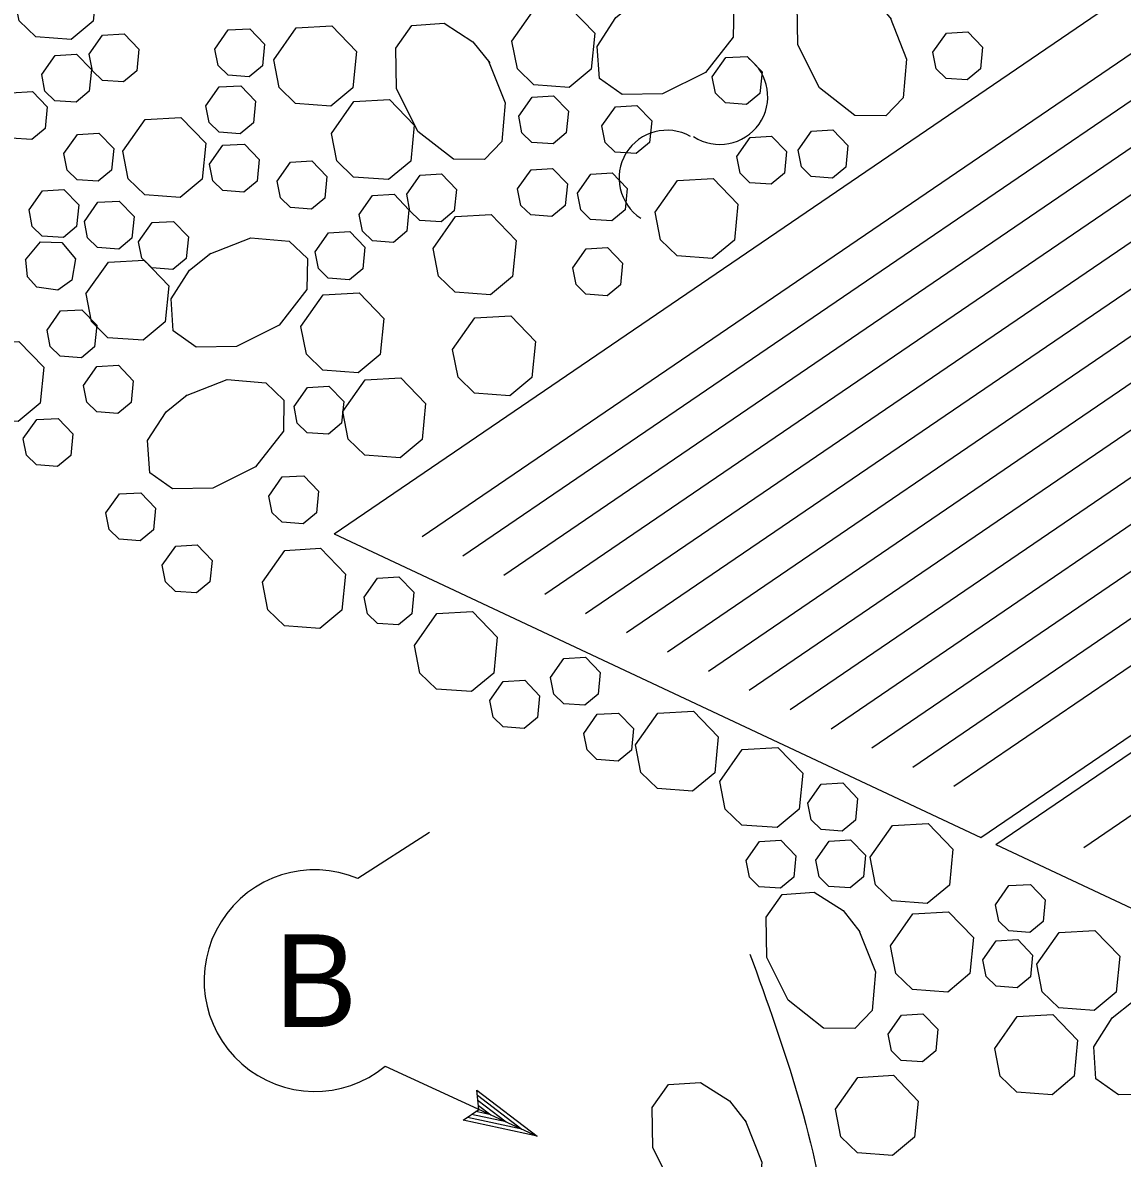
# Model space of a CAD drawing. Extents: x 6707406 to 6714471, y 1868570 to 1872341.
# Drawn here: x 6709742.1 to 6709827.6, y 1870177.2 to 1870265.6 of the extents above; entities that cross this region are included whole.
import ezdxf

# ---------------------------------------------------------------- set-up
doc = ezdxf.new("R2010")
doc.units = 0
for name, color, linetype in [('56 Stg 3 Anno', 7, 'Continuous'), ('57 Undefined', 7, 'Continuous'), ('60 Nongeo Data', 7, 'Continuous')]:
    doc.layers.add(name, color=color, linetype=linetype)

msp = doc.modelspace()

# ---------------------------------------------------------------- linework, layer by layer
at = {"layer": '56 Stg 3 Anno'}
for p, q in [((6709773.692, 1870202.586), (6709768.131, 1870199.006)), ((6709770.255, 1870184.412), (6709782.088, 1870178.964)), ((6709777.549, 1870181.053), (6709777.39, 1870182.544)), ((6709777.39, 1870182.544), (6709777.39, 1870182.544)), ((6709777.39, 1870182.544), (6709782.088, 1870178.964)), ((6709777.435, 1870182.146), (6709780.884, 1870179.519)), ((6709777.496, 1870181.738), (6709779.677, 1870180.075)), ((6709776.318, 1870180.214), (6709777.549, 1870181.053)), ((6709778.472, 1870180.632), (6709777.31, 1870180.883)), ((6709777.511, 1870181.365), (6709778.472, 1870180.632)), ((6709782.088, 1870178.964), (6709776.318, 1870180.214)), ((6709776.318, 1870180.214), (6709776.318, 1870180.214)), ((6709780.872, 1870179.52), (6709776.666, 1870180.433)), ((6709779.677, 1870180.075), (6709776.96, 1870180.664)), ((6709782.088, 1870178.964), (6709782.088, 1870178.964))]:
    msp.add_line(p, q, dxfattribs=at)
msp.add_arc((6709764.782, 1870191.067), 8.617, 67.12615, 309.43269, dxfattribs=at)
at = {"layer": '60 Nongeo Data'}
for p, q in [((6709766.295, 1870225.831), (6709844.223, 1870278.945)), ((6709773.125, 1870225.604), (6709845.802, 1870275.139)), ((6709776.307, 1870224.111), (6709848.983, 1870273.644)), ((6709779.488, 1870222.617), (6709852.164, 1870272.151)), ((6709782.67, 1870221.123), (6709855.345, 1870270.657)), ((6709785.85, 1870219.629), (6709858.526, 1870269.163)), ((6709789.032, 1870218.135), (6709861.708, 1870267.67)), ((6709792.212, 1870216.642), (6709864.888, 1870266.176)), ((6709795.394, 1870215.148), (6709868.07, 1870264.682)), ((6709798.575, 1870213.654), (6709871.251, 1870263.189)), ((6709801.757, 1870212.16), (6709874.433, 1870261.694)), ((6709804.938, 1870210.666), (6709877.614, 1870260.2)), ((6709808.119, 1870209.172), (6709880.795, 1870258.707)), ((6709811.3, 1870207.679), (6709883.975, 1870257.213)), ((6709814.481, 1870206.185), (6709887.158, 1870255.719)), ((6709816.605, 1870202.207), (6709894.532, 1870255.321)), ((6709817.773, 1870201.659), (6709895.701, 1870254.773)), ((6709824.603, 1870201.432), (6709897.278, 1870250.967)), ((6709766.295, 1870225.831), (6709816.605, 1870202.207)), ((6709817.773, 1870201.659), (6709868.082, 1870178.035))]:
    msp.add_line(p, q, dxfattribs=at)
for points in [[(6709741.368, 1870267.869), (6709743.108, 1870270.344), (6709745.884, 1870270.503), (6709747.816, 1870268.501), (6709747.536, 1870265.696), (6709745.821, 1870264.269), (6709743.078, 1870264.469), (6709741.789, 1870265.719), (6709741.37, 1870267.869)], [(6709789.703, 1870267.206), (6709792.956, 1870268.496), (6709795.946, 1870268.237), (6709797.366, 1870266.887), (6709797.321, 1870264.461), (6709795.165, 1870261.706), (6709791.832, 1870260.039), (6709788.693, 1870259.984), (6709786.925, 1870261.24), (6709786.757, 1870263.742), (6709788.192, 1870265.979), (6709789.835, 1870267.289)], [(6709809.532, 1870265.987), (6709810.822, 1870262.734), (6709810.563, 1870259.744), (6709809.212, 1870258.324), (6709806.788, 1870258.369), (6709804.032, 1870260.525), (6709802.365, 1870263.858), (6709802.31, 1870266.998), (6709803.566, 1870268.765), (6709806.068, 1870268.933), (6709808.304, 1870267.499), (6709809.615, 1870265.856)], [(6709780.115, 1870264.136), (6709781.855, 1870266.611), (6709784.631, 1870266.77), (6709786.562, 1870264.767), (6709786.283, 1870261.963), (6709784.567, 1870260.536), (6709781.825, 1870260.735), (6709780.535, 1870261.986), (6709780.116, 1870264.136)], [(6709778.304, 1870262.592), (6709779.594, 1870259.338), (6709779.335, 1870256.349), (6709777.985, 1870254.928), (6709775.559, 1870254.973), (6709772.804, 1870257.13), (6709771.138, 1870260.463), (6709771.082, 1870263.602), (6709772.338, 1870265.37), (6709774.84, 1870265.537), (6709777.077, 1870264.104), (6709778.387, 1870262.461)], [(6709747.226, 1870263.137), (6709748.27, 1870264.621), (6709749.936, 1870264.717), (6709751.095, 1870263.515), (6709750.927, 1870261.833), (6709749.899, 1870260.977), (6709748.252, 1870261.096), (6709747.478, 1870261.846), (6709747.227, 1870263.136)], [(6709757.001, 1870263.53), (6709758.045, 1870265.014), (6709759.712, 1870265.11), (6709760.87, 1870263.908), (6709760.702, 1870262.227), (6709759.674, 1870261.37), (6709758.028, 1870261.489), (6709757.254, 1870262.24), (6709757.003, 1870263.53)], [(6709761.578, 1870262.701), (6709763.317, 1870265.175), (6709766.094, 1870265.334), (6709768.024, 1870263.333), (6709767.745, 1870260.527), (6709766.03, 1870259.1), (6709763.287, 1870259.299), (6709761.997, 1870260.55), (6709761.58, 1870262.7)], [(6709812.868, 1870263.288), (6709813.912, 1870264.773), (6709815.578, 1870264.868), (6709816.736, 1870263.667), (6709816.569, 1870261.984), (6709815.539, 1870261.129), (6709813.894, 1870261.247), (6709813.121, 1870261.998), (6709812.869, 1870263.288)], [(6709743.53, 1870261.552), (6709744.574, 1870263.036), (6709746.24, 1870263.132), (6709747.399, 1870261.93), (6709747.23, 1870260.248), (6709746.202, 1870259.392), (6709744.556, 1870259.511), (6709743.782, 1870260.261), (6709743.531, 1870261.551)], [(6709795.702, 1870261.381), (6709796.747, 1870262.865), (6709798.413, 1870262.96), (6709799.571, 1870261.76), (6709799.403, 1870260.077), (6709798.374, 1870259.22), (6709796.728, 1870259.34), (6709795.954, 1870260.09), (6709795.703, 1870261.381)], [(6709740.098, 1870258.647), (6709741.142, 1870260.13), (6709742.808, 1870260.226), (6709743.967, 1870259.024), (6709743.799, 1870257.343), (6709742.771, 1870256.486), (6709741.124, 1870256.606), (6709740.35, 1870257.356), (6709740.099, 1870258.646)], [(6709756.305, 1870259.102), (6709757.349, 1870260.587), (6709759.015, 1870260.682), (6709760.173, 1870259.481), (6709760.006, 1870257.798), (6709758.976, 1870256.941), (6709757.331, 1870257.062), (6709756.557, 1870257.812), (6709756.306, 1870259.102)], [(6709766.072, 1870256.974), (6709767.812, 1870259.449), (6709770.588, 1870259.608), (6709772.519, 1870257.605), (6709772.24, 1870254.801), (6709770.524, 1870253.374), (6709767.782, 1870253.573), (6709766.492, 1870254.824), (6709766.074, 1870256.974)], [(6709780.642, 1870258.316), (6709781.686, 1870259.8), (6709783.352, 1870259.896), (6709784.511, 1870258.694), (6709784.343, 1870257.012), (6709783.315, 1870256.156), (6709781.668, 1870256.275), (6709780.894, 1870257.025), (6709780.643, 1870258.315)], [(6709787.12, 1870257.564), (6709788.164, 1870259.049), (6709789.83, 1870259.144), (6709790.988, 1870257.943), (6709790.821, 1870256.26), (6709789.791, 1870255.404), (6709788.145, 1870255.523), (6709787.372, 1870256.273), (6709787.121, 1870257.564)], [(6709749.842, 1870255.58), (6709751.58, 1870258.054), (6709754.358, 1870258.213), (6709756.288, 1870256.212), (6709756.008, 1870253.406), (6709754.293, 1870251.979), (6709751.551, 1870252.179), (6709750.261, 1870253.429), (6709749.843, 1870255.579)], [(6709745.265, 1870255.411), (6709746.309, 1870256.895), (6709747.975, 1870256.991), (6709749.134, 1870255.789), (6709748.965, 1870254.107), (6709747.937, 1870253.25), (6709746.291, 1870253.37), (6709745.517, 1870254.12), (6709745.266, 1870255.41)], [(6709797.61, 1870255.179), (6709798.654, 1870256.663), (6709800.32, 1870256.758), (6709801.478, 1870255.557), (6709801.311, 1870253.875), (6709800.281, 1870253.019), (6709798.635, 1870253.137), (6709797.862, 1870253.888), (6709797.611, 1870255.179)], [(6709802.378, 1870255.657), (6709803.422, 1870257.141), (6709805.088, 1870257.235), (6709806.246, 1870256.035), (6709806.079, 1870254.352), (6709805.049, 1870253.496), (6709803.404, 1870253.615), (6709802.63, 1870254.366), (6709802.379, 1870255.657)], [(6709756.589, 1870254.564), (6709757.633, 1870256.049), (6709759.299, 1870256.143), (6709760.457, 1870254.943), (6709760.29, 1870253.26), (6709759.26, 1870252.404), (6709757.615, 1870252.523), (6709756.841, 1870253.273), (6709756.591, 1870254.564)], [(6709761.849, 1870253.245), (6709762.893, 1870254.73), (6709764.559, 1870254.825), (6709765.717, 1870253.624), (6709765.55, 1870251.941), (6709764.521, 1870251.085), (6709762.875, 1870251.205), (6709762.101, 1870251.955), (6709761.85, 1870253.245)], [(6709780.559, 1870252.664), (6709781.602, 1870254.148), (6709783.269, 1870254.245), (6709784.427, 1870253.042), (6709784.259, 1870251.36), (6709783.231, 1870250.504), (6709781.584, 1870250.623), (6709780.811, 1870251.373), (6709780.56, 1870252.663)], [(6709771.93, 1870252.241), (6709772.974, 1870253.725), (6709774.64, 1870253.821), (6709775.799, 1870252.619), (6709775.63, 1870250.937), (6709774.602, 1870250.081), (6709772.956, 1870250.2), (6709772.182, 1870250.95), (6709771.931, 1870252.241)], [(6709785.212, 1870252.317), (6709786.257, 1870253.801), (6709787.923, 1870253.896), (6709789.081, 1870252.695), (6709788.913, 1870251.012), (6709787.884, 1870250.156), (6709786.238, 1870250.275), (6709785.465, 1870251.026), (6709785.213, 1870252.317)], [(6709791.251, 1870250.839), (6709792.989, 1870253.313), (6709795.767, 1870253.471), (6709797.696, 1870251.47), (6709797.417, 1870248.666), (6709795.702, 1870247.239), (6709792.96, 1870247.437), (6709791.669, 1870248.688), (6709791.252, 1870250.839)], [(6709742.549, 1870251.029), (6709743.591, 1870252.512), (6709745.259, 1870252.608), (6709746.416, 1870251.406), (6709746.249, 1870249.724), (6709745.22, 1870248.868), (6709743.574, 1870248.987), (6709742.799, 1870249.737), (6709742.549, 1870251.027)], [(6709768.233, 1870250.656), (6709769.277, 1870252.14), (6709770.944, 1870252.236), (6709772.103, 1870251.034), (6709771.934, 1870249.353), (6709770.906, 1870248.496), (6709769.26, 1870248.615), (6709768.486, 1870249.365), (6709768.235, 1870250.656)], [(6709746.849, 1870250.128), (6709747.893, 1870251.612), (6709749.559, 1870251.708), (6709750.718, 1870250.506), (6709750.55, 1870248.825), (6709749.522, 1870247.968), (6709747.875, 1870248.087), (6709747.101, 1870248.837), (6709746.85, 1870250.127)], [(6709773.994, 1870248.018), (6709775.732, 1870250.493), (6709778.51, 1870250.65), (6709780.441, 1870248.649), (6709780.162, 1870245.845), (6709778.447, 1870244.418), (6709775.704, 1870244.616), (6709774.414, 1870245.867), (6709773.995, 1870248.018)], [(6709751.073, 1870248.544), (6709752.117, 1870250.027), (6709753.783, 1870250.123), (6709754.942, 1870248.921), (6709754.774, 1870247.24), (6709753.746, 1870246.383), (6709752.099, 1870246.503), (6709751.325, 1870247.253), (6709751.074, 1870248.543)], [(6709756.551, 1870247.566), (6709759.804, 1870248.856), (6709762.793, 1870248.598), (6709764.213, 1870247.247), (6709764.168, 1870244.822), (6709762.012, 1870242.066), (6709758.679, 1870240.399), (6709755.54, 1870240.344), (6709753.772, 1870241.6), (6709753.605, 1870244.102), (6709755.039, 1870246.339), (6709756.682, 1870247.649)], [(6709764.802, 1870247.751), (6709765.846, 1870249.235), (6709767.512, 1870249.331), (6709768.671, 1870248.129), (6709768.502, 1870246.447), (6709767.474, 1870245.591), (6709765.828, 1870245.71), (6709765.054, 1870246.46), (6709764.803, 1870247.75)], [(6709742.282, 1870247.128), (6709743.438, 1870248.527), (6709745.106, 1870248.493), (6709746.169, 1870247.205), (6709745.871, 1870245.542), (6709744.78, 1870244.767), (6709743.149, 1870245.013), (6709742.434, 1870245.821), (6709742.284, 1870247.126)], [(6709784.851, 1870246.506), (6709785.894, 1870247.99), (6709787.56, 1870248.085), (6709788.718, 1870246.884), (6709788.551, 1870245.201), (6709787.521, 1870244.345), (6709785.876, 1870244.464), (6709785.103, 1870245.215), (6709784.852, 1870246.506)], [(6709746.977, 1870244.482), (6709748.717, 1870246.957), (6709751.494, 1870247.115), (6709753.424, 1870245.114), (6709753.144, 1870242.309), (6709751.429, 1870240.882), (6709748.688, 1870241.08), (6709747.398, 1870242.331), (6709746.979, 1870244.482)], [(6709763.702, 1870241.948), (6709765.44, 1870244.424), (6709768.218, 1870244.581), (6709770.149, 1870242.58), (6709769.87, 1870239.775), (6709768.154, 1870238.348), (6709765.412, 1870238.546), (6709764.122, 1870239.797), (6709763.703, 1870241.948)], [(6709743.945, 1870241.676), (6709744.989, 1870243.16), (6709746.655, 1870243.256), (6709747.814, 1870242.054), (6709747.645, 1870240.373), (6709746.617, 1870239.516), (6709744.971, 1870239.635), (6709744.197, 1870240.385), (6709743.946, 1870241.676)], [(6709775.499, 1870240.157), (6709777.238, 1870242.632), (6709780.016, 1870242.79), (6709781.946, 1870240.789), (6709781.666, 1870237.984), (6709779.951, 1870236.557), (6709777.209, 1870236.755), (6709775.92, 1870238.006), (6709775.501, 1870240.157)], [(6709737.249, 1870238.153), (6709738.989, 1870240.628), (6709741.764, 1870240.787), (6709743.696, 1870238.784), (6709743.417, 1870235.98), (6709741.701, 1870234.553), (6709738.959, 1870234.752), (6709737.669, 1870236.003), (6709737.25, 1870238.153)], [(6709746.788, 1870237.35), (6709747.832, 1870238.834), (6709749.498, 1870238.93), (6709750.657, 1870237.728), (6709750.489, 1870236.046), (6709749.461, 1870235.19), (6709747.814, 1870235.309), (6709747.041, 1870236.059), (6709746.789, 1870237.349)], [(6709754.713, 1870236.544), (6709757.966, 1870237.833), (6709760.956, 1870237.575), (6709762.377, 1870236.224), (6709762.331, 1870233.799), (6709760.175, 1870231.044), (6709756.843, 1870229.377), (6709753.703, 1870229.321), (6709751.935, 1870230.578), (6709751.768, 1870233.079), (6709753.202, 1870235.316), (6709754.845, 1870236.627)], [(6709763.165, 1870235.725), (6709764.209, 1870237.209), (6709765.875, 1870237.304), (6709767.033, 1870236.103), (6709766.866, 1870234.421), (6709765.836, 1870233.565), (6709764.191, 1870233.683), (6709763.417, 1870234.434), (6709763.166, 1870235.725)], [(6709766.955, 1870235.33), (6709768.695, 1870237.805), (6709771.471, 1870237.964), (6709773.402, 1870235.961), (6709773.123, 1870233.156), (6709771.408, 1870231.73), (6709768.665, 1870231.929), (6709767.376, 1870233.18), (6709766.956, 1870235.33)], [(6709742.097, 1870233.225), (6709743.141, 1870234.708), (6709744.807, 1870234.805), (6709745.966, 1870233.602), (6709745.798, 1870231.921), (6709744.77, 1870231.064), (6709743.123, 1870231.183), (6709742.349, 1870231.934), (6709742.098, 1870233.224)], [(6709761.207, 1870228.757), (6709762.251, 1870230.243), (6709763.917, 1870230.338), (6709765.075, 1870229.136), (6709764.908, 1870227.454), (6709763.878, 1870226.597), (6709762.233, 1870226.718), (6709761.459, 1870227.468), (6709761.208, 1870228.757)], [(6709748.529, 1870227.443), (6709749.573, 1870228.928), (6709751.239, 1870229.023), (6709752.397, 1870227.822), (6709752.23, 1870226.139), (6709751.2, 1870225.282), (6709749.555, 1870225.403), (6709748.781, 1870226.153), (6709748.53, 1870227.443)], [(6709752.914, 1870223.381), (6709753.958, 1870224.865), (6709755.625, 1870224.961), (6709756.784, 1870223.759), (6709756.615, 1870222.077), (6709755.587, 1870221.221), (6709753.941, 1870221.34), (6709753.167, 1870222.09), (6709752.916, 1870223.38)], [(6709760.713, 1870222.063), (6709762.451, 1870224.537), (6709765.229, 1870224.695), (6709767.159, 1870222.694), (6709766.879, 1870219.889), (6709765.164, 1870218.463), (6709762.423, 1870218.66), (6709761.132, 1870219.911), (6709760.714, 1870222.063)], [(6709768.618, 1870220.9), (6709769.662, 1870222.385), (6709771.328, 1870222.48), (6709772.486, 1870221.279), (6709772.319, 1870219.596), (6709771.289, 1870218.74), (6709769.644, 1870218.859), (6709768.87, 1870219.609), (6709768.619, 1870220.9)], [(6709772.529, 1870217.146), (6709774.267, 1870219.62), (6709777.045, 1870219.778), (6709778.975, 1870217.777), (6709778.695, 1870214.973), (6709776.98, 1870213.546), (6709774.239, 1870213.744), (6709772.948, 1870214.994), (6709772.53, 1870217.146)], [(6709783.121, 1870214.645), (6709784.164, 1870216.13), (6709785.831, 1870216.224), (6709786.988, 1870215.024), (6709786.821, 1870213.341), (6709785.792, 1870212.485), (6709784.146, 1870212.604), (6709783.373, 1870213.354), (6709783.122, 1870214.645)], [(6709778.398, 1870212.85), (6709779.442, 1870214.334), (6709781.108, 1870214.43), (6709782.267, 1870213.228), (6709782.099, 1870211.546), (6709781.071, 1870210.69), (6709779.424, 1870210.809), (6709778.65, 1870211.559), (6709778.399, 1870212.849)], [(6709785.705, 1870210.301), (6709786.749, 1870211.785), (6709788.416, 1870211.881), (6709789.575, 1870210.679), (6709789.406, 1870208.998), (6709788.378, 1870208.141), (6709786.732, 1870208.261), (6709785.957, 1870209.011), (6709785.706, 1870210.3)], [(6709789.722, 1870209.406), (6709791.461, 1870211.88), (6709794.238, 1870212.038), (6709796.168, 1870210.037), (6709795.889, 1870207.232), (6709794.174, 1870205.806), (6709791.432, 1870206.004), (6709790.141, 1870207.254), (6709789.724, 1870209.406)], [(6709796.296, 1870206.567), (6709798.034, 1870209.041), (6709800.812, 1870209.199), (6709802.742, 1870207.198), (6709802.463, 1870204.394), (6709800.747, 1870202.967), (6709798.006, 1870203.165), (6709796.716, 1870204.416), (6709796.297, 1870206.567)], [(6709803.138, 1870204.862), (6709804.182, 1870206.346), (6709805.848, 1870206.441), (6709807.006, 1870205.24), (6709806.839, 1870203.557), (6709805.81, 1870202.701), (6709804.164, 1870202.82), (6709803.39, 1870203.571), (6709803.139, 1870204.862)], [(6709807.976, 1870200.663), (6709809.716, 1870203.138), (6709812.493, 1870203.297), (6709814.424, 1870201.295), (6709814.144, 1870198.49), (6709812.429, 1870197.063), (6709809.686, 1870197.263), (6709808.397, 1870198.513), (6709807.978, 1870200.663)], [(6709798.334, 1870200.408), (6709799.378, 1870201.893), (6709801.045, 1870201.988), (6709802.202, 1870200.787), (6709802.035, 1870199.104), (6709801.006, 1870198.248), (6709799.36, 1870198.367), (6709798.587, 1870199.117), (6709798.336, 1870200.408)], [(6709803.752, 1870200.439), (6709804.796, 1870201.923), (6709806.463, 1870202.018), (6709807.62, 1870200.817), (6709807.453, 1870199.135), (6709806.424, 1870198.279), (6709804.778, 1870198.397), (6709804.005, 1870199.148), (6709803.754, 1870200.439)], [(6709817.734, 1870196.975), (6709818.778, 1870198.46), (6709820.445, 1870198.555), (6709821.602, 1870197.354), (6709821.435, 1870195.671), (6709820.406, 1870194.816), (6709818.76, 1870194.934), (6709817.987, 1870195.685), (6709817.736, 1870196.975)], [(6709807.104, 1870195), (6709808.393, 1870191.747), (6709808.134, 1870188.757), (6709806.784, 1870187.337), (6709804.359, 1870187.382), (6709801.603, 1870189.538), (6709799.937, 1870192.871), (6709799.881, 1870196.01), (6709801.138, 1870197.779), (6709803.639, 1870197.945), (6709805.876, 1870196.513), (6709807.186, 1870194.869)], [(6709809.573, 1870193.783), (6709811.313, 1870196.258), (6709814.089, 1870196.417), (6709816.02, 1870194.414), (6709815.741, 1870191.61), (6709814.026, 1870190.183), (6709811.283, 1870190.382), (6709809.994, 1870191.633), (6709809.574, 1870193.783)], [(6709820.951, 1870192.343), (6709822.691, 1870194.818), (6709825.467, 1870194.977), (6709827.399, 1870192.974), (6709827.119, 1870190.17), (6709825.404, 1870188.743), (6709822.661, 1870188.942), (6709821.372, 1870190.193), (6709820.953, 1870192.343)], [(6709816.752, 1870192.676), (6709817.796, 1870194.16), (6709819.462, 1870194.255), (6709820.62, 1870193.054), (6709820.452, 1870191.371), (6709819.423, 1870190.515), (6709817.777, 1870190.634), (6709817.004, 1870191.385), (6709816.753, 1870192.676)], [(6709828.323, 1870189.396), (6709831.577, 1870190.686), (6709834.566, 1870190.427), (6709835.987, 1870189.077), (6709835.942, 1870186.651), (6709833.785, 1870183.896), (6709830.453, 1870182.229), (6709827.314, 1870182.173), (6709825.545, 1870183.43), (6709825.378, 1870185.931), (6709826.813, 1870188.168), (6709828.456, 1870189.479)], [(6709809.383, 1870186.901), (6709810.427, 1870188.386), (6709812.093, 1870188.48), (6709813.251, 1870187.28), (6709813.084, 1870185.597), (6709812.054, 1870184.741), (6709810.408, 1870184.86), (6709809.635, 1870185.61), (6709809.385, 1870186.901)], [(6709817.678, 1870185.797), (6709819.418, 1870188.272), (6709822.195, 1870188.431), (6709824.126, 1870186.428), (6709823.846, 1870183.624), (6709822.131, 1870182.197), (6709819.388, 1870182.396), (6709818.099, 1870183.647), (6709817.68, 1870185.797)], [(6709805.277, 1870181.068), (6709807.017, 1870183.542), (6709809.793, 1870183.702), (6709811.724, 1870181.699), (6709811.445, 1870178.894), (6709809.729, 1870177.468), (6709806.987, 1870177.667), (6709805.697, 1870178.918), (6709805.278, 1870181.068)], [(6709798.257, 1870180.201), (6709799.546, 1870176.948), (6709799.287, 1870173.958), (6709797.937, 1870172.538), (6709795.512, 1870172.583), (6709792.756, 1870174.739), (6709791.089, 1870178.072), (6709791.034, 1870181.211), (6709792.29, 1870182.98), (6709794.792, 1870183.146), (6709797.028, 1870181.713), (6709798.339, 1870180.07)]]:
    msp.add_lwpolyline(points, dxfattribs=at)
for centre, start, end in [((6709796.291, 1870259.833), 236.78307, 53.14356), ((6709792.168, 1870253.494), 60.49863, 236.85912)]:
    msp.add_arc(centre, 3.722, start, end, dxfattribs=at)
msp.add_spline([(6709798.634, 1870193.136), (6709804.765, 1870170.353), (6709801.845, 1870151.66), (6709789.875, 1870139.977)], degree=3, dxfattribs=at)

# ---------------------------------------------------------------- texts
at = {"layer": '57 Undefined'}
msp.add_text('B', height=7.206, dxfattribs=at).set_placement((6709761.647, 1870187.464))

doc.saveas('drawing.dxf')
